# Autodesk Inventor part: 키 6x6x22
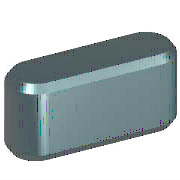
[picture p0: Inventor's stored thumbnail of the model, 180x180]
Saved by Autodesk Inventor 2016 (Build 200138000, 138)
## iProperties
IsCustomPart: 1
Created: 2012-02
Part Number: 키 6x6x22
Material: 강철, 연강
Description: 키 및 해당 키홈
Document SubType Name: Modeling
Standard: KS B 1311
Designer: mduedu
Standards Organization: KS
Language: ko-KR
Size Designation: 6 x 6 x 22
Categories: <MemberInstance><Categories><Category DisplayName="샤프트 부품" InternalName="7f7aeb1f-a693-4053-b835-cee3144e0d98" Mnemonic="SHFT"><Category DisplayName="키" Interna
Density: 7.86 g/cm^3
Mass: 5.79788 g
Surface Area: 5.294 cm^2
Volume: 0.737644 cm^3
Appearance: 노란색
Author: mduedu
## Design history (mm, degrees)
workplane "Work Plane1"
workplane "Work Plane2"
sketch "스케치1"
  geometry: L1 (3, 3)-(19, 3); L2 (19, -3)-(3, -3); L3 (0, 9.4)-(0, -7.4) reference; L4 (-5, 0)-(30, 0) reference; L5 (22, 0)-(22, 7); A1 r 3 centre (3, 0) between (3, 3) and (3, -3); A2 r 3 centre (19, 0) between (19, -3) and (19, 3)
  constraints: 6 end point, 5 point on circle, 4 tangent, 3 point on line, 2 centre point, 1 horizontal, 1 parallel, 1 perpendicular
  dimensions: "d0" = 3 radius of A1 (= 0.5 x PB); "d13" = 3 radius of A2 (= 0.5 x PB); "d14" = 22 distance between parallel lines of L5 L3 (= NLG)
extrude "본체1" new body sketch "스케치1" taper "d3" = 0 deg; stored distance "d4" = 10
workplane "Work Plane3"
body "Solid1"
chamfer "모따기1" distance "d8" = 0.4 (= PHH); stored, may be unused: second distance "d9" = 0.4 (= PHH), angle "d15" = 45 deg
other parameters: "d1" = -3.5 (= -PNT), "d2" = 2.5 (= PH - PNT), "NLG" = 22 [user parameter; used in 3 equation terms], "PB" = 6 [user parameter; used in 2 equation terms], "PNT" = 3.5 [user parameter; used in 2 equation terms], "PH" = 6 [user parameter; used in 1 equation term], "PHH" = 0.4 [user parameter; used in 2 equation terms], "d10" = 0, "d16" = 0, "d17" = 0, "d18" = 0, "WDMIN" = 17 [user parameter], "PLB2" = 22 (= NLG) [user parameter], "WDMAX" = 22 [user parameter], "PLB1" = 22 (= NLG) [user parameter], "RR" = 0.16 [user parameter], "PUEB" = 2.8 [user parameter]
